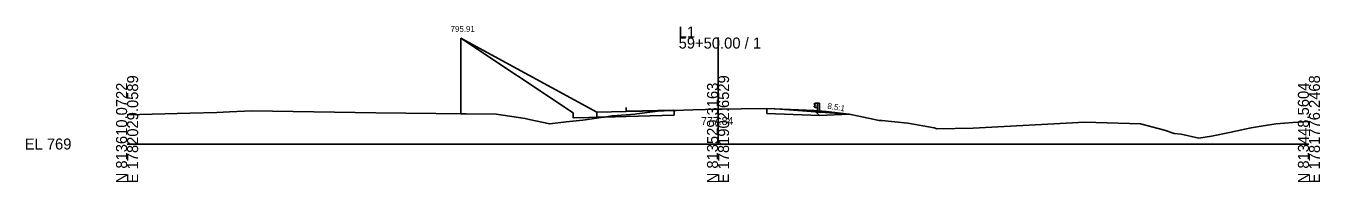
# Model space of a CAD drawing. Extents: x 5574 to 10203, y -10 to 9546.
# Drawn here: x 6574.3 to 6902.8, y 6490.3 to 6530 of the extents above; entities that cross this region are included whole.
import ezdxf

# ---------------------------------------------------------------- set-up
doc = ezdxf.new("R2010")
doc.units = 0
for name, color, linetype in [('Exist Cross Section Cell', 7, 'Continuous'), ('Exist XS Center Line Elevation Label', 7, 'Continuous'), ('Exist XS Ground Line', 7, 'Continuous'), ('Prop XS Ditch Slope Text', 7, 'Continuous'), ('Prop XS Ditch Standard Text', 7, 'Continuous'), ('Prop XS Dump Level', 7, 'Continuous'), ('Prop XS Earthwork Shape', 7, 'Continuous'), ('Prop XS EOT Tick Mark', 7, 'Continuous'), ('Prop XS Finish Grade', 7, 'Continuous'), ('Prop XS Finish Grade Earthwork', 7, 'Continuous'), ('Prop XS Finish Grade Paved Shoulder', 7, 'Continuous'), ('Prop XS Finish Grade Pavement', 7, 'Continuous'), ('Prop XS Guardrail', 7, 'Continuous'), ('Prop XS Pvmt Edge Slope', 7, 'Continuous'), ('Prop XS Subgrade Earthwork', 7, 'Continuous'), ('Scratch_Level_3', 7, 'Continuous'), ('Scratch_Level_6', 7, 'Continuous')]:
    doc.layers.add(name, color=color, linetype=linetype)

msp = doc.modelspace()

# ---------------------------------------------------------------- linework, layer by layer
at = {"layer": 'Exist Cross Section Cell'}
for p, q in [((6750, 6500), (6750, 6527.07)), ((6600, 6500), (6750, 6500)), ((6750, 6500), (6900, 6500))]:
    msp.add_line(p, q, dxfattribs=at)
at = {"layer": 'Exist XS Ground Line'}
for p, q in [((6626, 6508.22), (6631.68, 6508.45)), ((6631.68, 6508.45), (6663.12, 6507.97)), ((6729.43, 6507.64), (6734.69, 6508.34)), ((6734.69, 6508.34), (6736.34, 6508.43)), ((6736.34, 6508.43), (6738.85, 6508.56)), ((6738.85, 6508.56), (6743.57, 6508.68)), ((6743.57, 6508.68), (6750, 6508.84)), ((6750, 6508.84), (6751.02, 6508.87)), ((6751.02, 6508.87), (6755.89, 6508.93)), ((6755.89, 6508.93), (6762.42, 6509.02)), ((6762.42, 6509.02), (6764.28, 6508.94)), ((6764.28, 6508.94), (6765.78, 6508.87)), ((6765.78, 6508.87), (6775.93, 6508.14)), ((6600, 6507.39), (6615.96, 6507.86)), ((6615.96, 6507.86), (6622.77, 6508.01)), ((6622.77, 6508.01), (6626, 6508.22)), ((6663.12, 6507.97), (6693.66, 6507.59)), ((6693.66, 6507.59), (6701.06, 6506.45)), ((6701.06, 6506.45), (6701.71, 6506.35)), ((6701.71, 6506.35), (6702.07, 6506.27)), ((6702.07, 6506.27), (6707.28, 6505.11)), ((6707.28, 6505.11), (6711.49, 6505.64)), ((6711.49, 6505.64), (6715.71, 6506.1)), ((6715.71, 6506.1), (6720.93, 6506.83)), ((6720.93, 6506.83), (6723.09, 6507.14)), ((6723.09, 6507.14), (6724.37, 6507.25)), ((6724.37, 6507.25), (6728.86, 6507.58)), ((6728.86, 6507.58), (6729.43, 6507.64)), ((6775.93, 6508.14), (6783.27, 6507.61)), ((6783.27, 6507.61), (6785.74, 6507.12)), ((6785.74, 6507.12), (6790.87, 6505.98)), ((6790.87, 6505.98), (6791.57, 6505.95)), ((6791.57, 6505.95), (6798.21, 6505.33)), ((6798.21, 6505.33), (6804.85, 6504.1)), ((6814.78, 6504.06), (6843.13, 6505.59)), ((6843.13, 6505.59), (6857.24, 6505.11)), ((6857.24, 6505.11), (6863.36, 6503.49)), ((6887.88, 6504.57), (6891.72, 6505.13)), ((6891.72, 6505.13), (6895.94, 6505.46)), ((6895.94, 6505.46), (6900, 6505.77)), ((6804.85, 6504.1), (6805.57, 6503.89)), ((6805.57, 6503.89), (6814.78, 6504.06)), ((6863.36, 6503.49), (6865.82, 6502.71)), ((6865.82, 6502.71), (6867.58, 6502.51)), ((6867.58, 6502.51), (6872.03, 6501.48)), ((6872.03, 6501.48), (6875.28, 6502.04)), ((6875.28, 6502.04), (6879.8, 6502.96)), ((6879.8, 6502.96), (6883.7, 6503.78)), ((6883.7, 6503.78), (6885.32, 6504.15)), ((6885.32, 6504.15), (6887.88, 6504.57))]:
    msp.add_line(p, q, dxfattribs=at)
at = {"layer": 'Prop XS Dump Level'}
msp.add_line((6738.82, 6508.62), (6726.71, 6508.37), dxfattribs=at)
msp.add_line((6738.82, 6508.62), (6726.71, 6508.37), dxfattribs=at)
at = {"layer": 'Prop XS Earthwork Shape'}
for points in [[(6693.66, 6507.59), (6701.06, 6506.45), (6701.71, 6506.35), (6702.07, 6506.27), (6707.28, 6505.11), (6711.49, 6505.64), (6715.71, 6506.1), (6720.93, 6506.83), (6721.18, 6506.87), (6713.21, 6506.67), (6713.21, 6507.92), (6684.72, 6526.91), (6684.72, 6507.7)], [(6738.88, 6507.31), (6738.88, 6508.56), (6738.85, 6508.56), (6736.34, 6508.43), (6734.69, 6508.34), (6729.43, 6507.64), (6728.86, 6507.58), (6724.37, 6507.25), (6723.09, 6507.14), (6721.18, 6506.87), (6726.71, 6507.01)], [(6762.42, 6507.77), (6775.73, 6507.24), (6783.27, 6507.61), (6775.93, 6508.14), (6765.78, 6508.87), (6764.28, 6508.94), (6762.42, 6509.02)]]:
    msp.add_lwpolyline(points, close=True, dxfattribs=at)
at = {"layer": 'Prop XS EOT Tick Mark'}
msp.add_line((6726.71, 6508.26), (6726.71, 6509.26), dxfattribs=at)
at = {"layer": 'Prop XS Finish Grade'}
for p, q in [((6774.42, 6508.54), (6777.42, 6508.3)), ((6777.42, 6508.3), (6783.27, 6507.61))]:
    msp.add_line(p, q, dxfattribs=at)
at = {"layer": 'Prop XS Finish Grade Earthwork'}
for p, q in [((6719.21, 6508.07), (6684.72, 6526.91)), ((6684.72, 6526.91), (6684.72, 6526.91)), ((6684.72, 6526.91), (6684.72, 6507.7))]:
    msp.add_line(p, q, dxfattribs=at)
at = {"layer": 'Prop XS Finish Grade Paved Shoulder'}
msp.add_line((6726.71, 6508.26), (6719.21, 6508.07), dxfattribs=at)
at = {"layer": 'Prop XS Finish Grade Pavement'}
for p, q in [((6738.88, 6508.56), (6726.71, 6508.26)), ((6762.42, 6509.02), (6774.42, 6508.54))]:
    msp.add_line(p, q, dxfattribs=at)
at = {"layer": 'Prop XS Guardrail'}
for p, q in [((6774.45, 6510.22), (6774.42, 6510.16)), ((6774.42, 6510.16), (6774.45, 6510.1)), ((6774.45, 6509.6), (6774.42, 6509.54)), ((6774.42, 6509.54), (6774.45, 6509.48)), ((6774.74, 6510.42), (6774.45, 6510.22)), ((6774.45, 6510.1), (6774.74, 6509.9)), ((6774.74, 6509.8), (6774.45, 6509.6)), ((6774.45, 6509.48), (6774.74, 6509.28)), ((6775.24, 6510.42), (6774.74, 6510.42)), ((6774.74, 6509.9), (6774.74, 6509.8)), ((6774.74, 6509.28), (6775.24, 6509.28)), ((6775.74, 6510.42), (6775.24, 6510.42)), ((6775.24, 6510.42), (6775.24, 6507.92)), ((6775.74, 6507.92), (6775.74, 6510.42))]:
    msp.add_line(p, q, dxfattribs=at)
at = {"layer": 'Prop XS Pvmt Edge Slope'}
msp.add_line((6774.42, 6508.54), (6775.73, 6507.24), dxfattribs=at)
at = {"layer": 'Prop XS Subgrade Earthwork'}
for p, q in [((6738.88, 6507.31), (6738.88, 6508.56)), ((6762.42, 6507.77), (6762.42, 6509.02)), ((6719.21, 6506.82), (6719.21, 6508.07)), ((6726.71, 6507.01), (6719.21, 6506.82)), ((6738.88, 6507.31), (6726.71, 6507.01)), ((6762.42, 6507.77), (6775.73, 6507.24)), ((6775.73, 6507.24), (6783.27, 6507.61))]:
    msp.add_line(p, q, dxfattribs=at)
at = {"layer": 'Scratch_Level_3'}
for p, q in [((6777.42, 6508.3), (6774.42, 6508.54)), ((6774.42, 6508.54), (6775.73, 6507.24)), ((6783.27, 6507.61), (6777.42, 6508.3)), ((6775.73, 6507.24), (6783.27, 6507.61))]:
    msp.add_line(p, q, dxfattribs=at)
at = {"layer": 'Scratch_Level_6'}
for points in [[(6738.88, 6507.31), (6726.71, 6507.01), (6721.18, 6506.87), (6723.09, 6507.14), (6724.37, 6507.25), (6728.86, 6507.58), (6729.43, 6507.64), (6734.69, 6508.34), (6736.34, 6508.43), (6738.85, 6508.56), (6738.88, 6508.56)], [(6762.42, 6507.77), (6762.42, 6509.02), (6764.28, 6508.94), (6765.78, 6508.87), (6775.93, 6508.14), (6783.27, 6507.61), (6775.73, 6507.24)]]:
    msp.add_lwpolyline(points, close=True, dxfattribs=at)

# ---------------------------------------------------------------- texts
at = {"layer": 'Exist Cross Section Cell'}
for s, p in [('L1', (6740, 6527.07)), ('59+50.00 / 1', (6740, 6524.27)), ('EL 769', (6574, 6498.6))]:
    msp.add_text(s, height=2.8, dxfattribs=at).set_placement(p)
for s, p in [('N 813610.0722', (6600, 6490)), ('E 1782029.0589', (6602.8, 6490)), ('N 813529.3163', (6750, 6490)), ('E 1781902.6529', (6752.8, 6490)), ('N 813448.5604', (6900, 6490)), ('E 1781776.2468', (6902.8, 6490))]:
    msp.add_text(s, height=2.8, rotation=90, dxfattribs=at).set_placement(p)
at = {"layer": 'Exist XS Center Line Elevation Label'}
msp.add_text('777.84', height=2, dxfattribs=at).set_placement((6745.72, 6504.84))
at = {"layer": 'Prop XS Ditch Slope Text'}
msp.add_text('8.5:1', height=1.5, rotation=350.46, dxfattribs=at).set_placement((6777.69, 6509))
at = {"layer": 'Prop XS Ditch Standard Text'}
msp.add_text('795.91', height=1.5, dxfattribs=at).set_placement((6682.13, 6528.52))
at = {"layer": 'Prop XS Dump Level'}
msp.add_text('Eop', height=0.3, dxfattribs=at).set_placement((6738.88, 6508.26))

doc.saveas('drawing.dxf')
